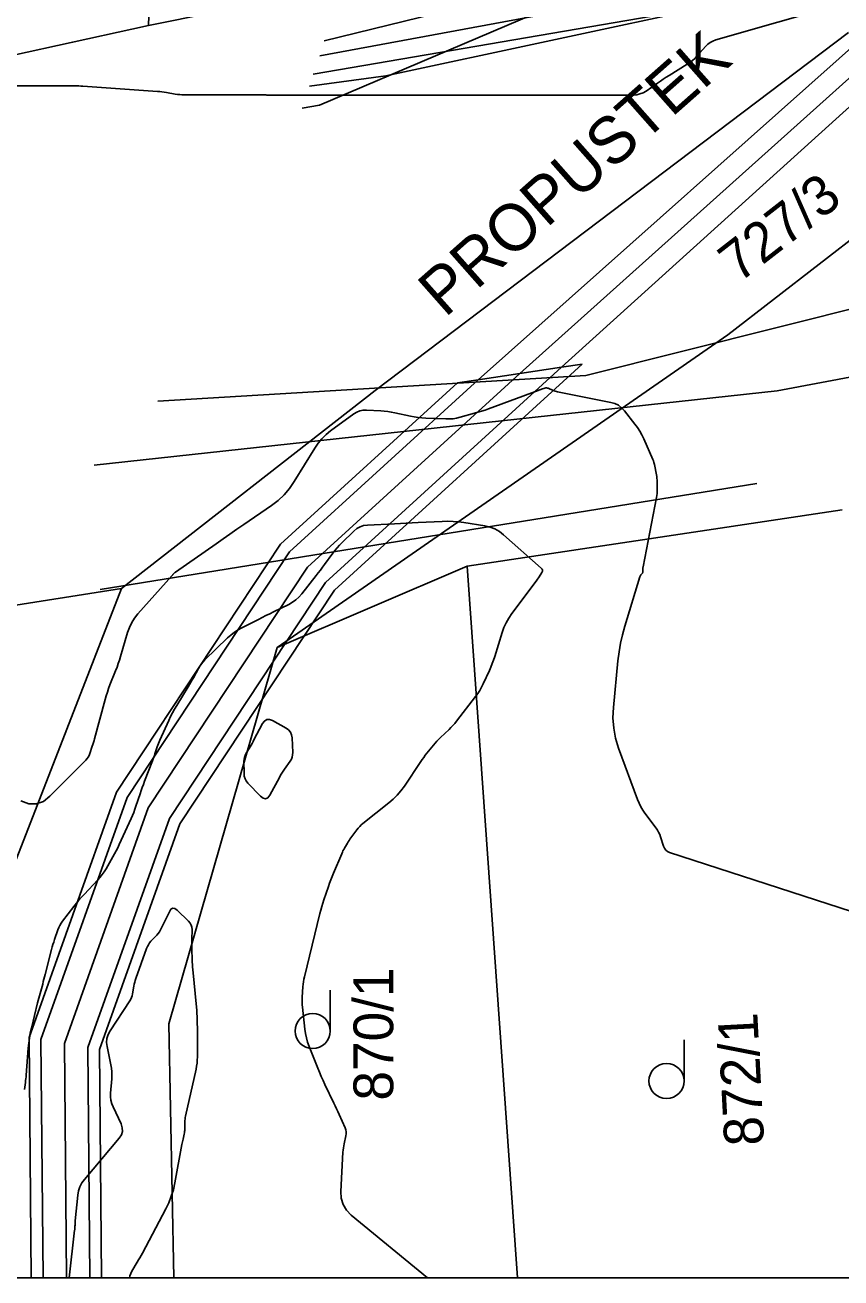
# Model space of a CAD drawing. Extents: x -534410 to -534262, y -1190162 to -1189584.
# Drawn here: x -534346.89 to -534329.45, y -1190161.97 to -1190135.2 of the extents above; entities that cross this region are included whole.
import ezdxf

# ---------------------------------------------------------------- set-up
doc = ezdxf.new("R2010")
doc.units = 0
for name, color, linetype in [('07_ELEKTRO', 7, 'Continuous'), ('14', 7, 'Continuous'), ('30', 7, 'Continuous'), ('31', 7, 'Continuous'), ('_N_osa', 7, 'Continuous'), ('_N_text', 7, 'Continuous'), ('_rámeček', 7, 'Continuous'), ('_rámeček_mřížka', 7, 'Continuous'), ('_tenka', 7, 'Continuous'), ('_tenká_čárkovaná', 7, 'Continuous'), ('Hranice parcel', 7, 'Continuous'), ('Parcelní čísla', 7, 'Continuous'), ('Vrstva 1', 7, 'Continuous'), ('Vrstva 2', 7, 'Continuous'), ('Značky kultur', 7, 'Continuous')]:
    doc.layers.add(name, color=color, linetype=linetype)

msp = doc.modelspace()

# ---------------------------------------------------------------- linework, layer by layer
at = {"layer": '07_ELEKTRO'}
for points in [[(-534340.501, -1190135.539), (-534331.273, -1190133.27), (-534330.81, -1190133.08), (-534330.32, -1190132.66), (-534330.24, -1190132.17), (-534330.24, -1190130.93), (-534330.14, -1190126.19), (-534329.99, -1190122.81), (-534329.79, -1190121.43), (-534329.75, -1190115.24), (-534329.64, -1190109.01), (-534329.39, -1190101.86), (-534329.4, -1190094.43), (-534329.31, -1190087.46), (-534329.03, -1190079.95)], [(-534331.25, -1190144.995), (-534345.285, -1190147.258)]]:
    msp.add_lwpolyline(points, dxfattribs=at)
at = {"layer": '14'}
msp.add_lwpolyline([(-534314.619, -1190129.669), (-534321.91, -1190130.93), (-534322.66, -1190131.1), (-534328.55, -1190132.02), (-534329.42, -1190132.15), (-534330.73, -1190132.71), (-534340.6, -1190136.91), (-534340.966, -1190136.972)], dxfattribs=at)
at = {"layer": '30'}
for points in [[(-534346.982, -1190151.777), (-534346.812, -1190151.837), (-534346.651, -1190151.841), (-534346.5, -1190151.787), (-534346.358, -1190151.677), (-534345.591, -1190150.904), (-534345.563, -1190150.873), (-534345.54, -1190150.84), (-534345.521, -1190150.804), (-534345.506, -1190150.765), (-534345.453, -1190150.607), (-534345.44, -1190150.568), (-534345.428, -1190150.528), (-534345.416, -1190150.488), (-534345.405, -1190150.448), (-534345.179, -1190149.609), (-534345.157, -1190149.53), (-534345.132, -1190149.453), (-534345.105, -1190149.376), (-534345.076, -1190149.299), (-534344.955, -1190148.996), (-534344.925, -1190148.92), (-534344.898, -1190148.843), (-534344.872, -1190148.766), (-534344.848, -1190148.688), (-534344.698, -1190148.178), (-534344.659, -1190148.069), (-534344.61, -1190147.967), (-534344.55, -1190147.872), (-534344.479, -1190147.782), (-534343.756, -1190146.965), (-534343.749, -1190146.958), (-534343.743, -1190146.951), (-534343.736, -1190146.944), (-534343.73, -1190146.938), (-534343.703, -1190146.912), (-534343.696, -1190146.905), (-534343.689, -1190146.899), (-534343.681, -1190146.893), (-534343.674, -1190146.888), (-534342.807, -1190146.281), (-534342.66, -1190146.178), (-534342.513, -1190146.075), (-534342.365, -1190145.973), (-534342.217, -1190145.871), (-534341.624, -1190145.464), (-534341.482, -1190145.356), (-534341.354, -1190145.235), (-534341.24, -1190145.101), (-534341.139, -1190144.954), (-534340.7, -1190144.239), (-534340.629, -1190144.134), (-534340.549, -1190144.038), (-534340.459, -1190143.95), (-534340.361, -1190143.87), (-534339.865, -1190143.506), (-534339.802, -1190143.468), (-534339.736, -1190143.441), (-534339.666, -1190143.427), (-534339.592, -1190143.425), (-534339.289, -1190143.442), (-534339.214, -1190143.447), (-534339.139, -1190143.456), (-534339.064, -1190143.468), (-534338.99, -1190143.483), (-534338.653, -1190143.557), (-534338.572, -1190143.573), (-534338.491, -1190143.586), (-534338.409, -1190143.594), (-534338.326, -1190143.599), (-534337.901, -1190143.616), (-534337.822, -1190143.616), (-534337.745, -1190143.61), (-534337.667, -1190143.598), (-534337.591, -1190143.579), (-534337.287, -1190143.495), (-534337.211, -1190143.473), (-534337.136, -1190143.45), (-534337.061, -1190143.424), (-534336.987, -1190143.398), (-534335.926, -1190143.004), (-534335.908, -1190142.998), (-534335.889, -1190142.991), (-534335.871, -1190142.985), (-534335.853, -1190142.979), (-534335.78, -1190142.956), (-534335.762, -1190142.952), (-534335.744, -1190142.951), (-534335.726, -1190142.954), (-534335.708, -1190142.96), (-534335.606, -1190143.006), (-534335.583, -1190143.016), (-534335.56, -1190143.024), (-534335.536, -1190143.031), (-534335.512, -1190143.037), (-534334.373, -1190143.26), (-534334.287, -1190143.284), (-534334.21, -1190143.322), (-534334.141, -1190143.374), (-534334.081, -1190143.439), (-534333.856, -1190143.727), (-534333.802, -1190143.801), (-534333.753, -1190143.877), (-534333.709, -1190143.957), (-534333.669, -1190144.039), (-534333.476, -1190144.478), (-534333.462, -1190144.513), (-534333.45, -1190144.548), (-534333.439, -1190144.585), (-534333.431, -1190144.621), (-534333.401, -1190144.77), (-534333.395, -1190144.807), (-534333.39, -1190144.845), (-534333.387, -1190144.882), (-534333.385, -1190144.92), (-534333.382, -1190145.116), (-534333.382, -1190145.162), (-534333.385, -1190145.207), (-534333.39, -1190145.251), (-534333.398, -1190145.296), (-534333.683, -1190146.773), (-534333.684, -1190146.78), (-534333.685, -1190146.787), (-534333.685, -1190146.794), (-534333.685, -1190146.802), (-534333.685, -1190146.831), (-534333.685, -1190146.844), (-534333.685, -1190146.858), (-534333.687, -1190146.886), (-534333.688, -1190146.893), (-534333.689, -1190146.899), (-534333.692, -1190146.905), (-534333.696, -1190146.911), (-534333.729, -1190146.949), (-534333.736, -1190146.958), (-534333.741, -1190146.967), (-534333.746, -1190146.976), (-534333.749, -1190146.986), (-534334.072, -1190148.046), (-534334.122, -1190148.227), (-534334.164, -1190148.409), (-534334.196, -1190148.594), (-534334.219, -1190148.78), (-534334.317, -1190149.782), (-534334.326, -1190150.003), (-534334.311, -1190150.221), (-534334.271, -1190150.435), (-534334.206, -1190150.647), (-534333.801, -1190151.749), (-534333.769, -1190151.826), (-534333.733, -1190151.9), (-534333.69, -1190151.972), (-534333.643, -1190152.041), (-534333.405, -1190152.36), (-534333.376, -1190152.403), (-534333.35, -1190152.448), (-534333.328, -1190152.495), (-534333.311, -1190152.544), (-534333.247, -1190152.744), (-534333.227, -1190152.79), (-534333.198, -1190152.828), (-534333.161, -1190152.857), (-534333.115, -1190152.877), (-534328.176, -1190154.481)], [(-534345.95, -1190161.97), (-534345.831, -1190160.952), (-534345.83, -1190160.941), (-534345.829, -1190160.93), (-534345.828, -1190160.919), (-534345.827, -1190160.909), (-534345.824, -1190160.864), (-534345.823, -1190160.844), (-534345.822, -1190160.825), (-534345.82, -1190160.787), (-534345.82, -1190160.778), (-534345.819, -1190160.768), (-534345.818, -1190160.759), (-534345.817, -1190160.749), (-534345.762, -1190160.199), (-534345.746, -1190160.107), (-534345.717, -1190160.02), (-534345.675, -1190159.939), (-534345.62, -1190159.863), (-534344.88, -1190158.985), (-534344.833, -1190158.913), (-534344.811, -1190158.838), (-534344.813, -1190158.76), (-534344.84, -1190158.678), (-534345.011, -1190158.317), (-534345.039, -1190158.247), (-534345.057, -1190158.174), (-534345.065, -1190158.1), (-534345.063, -1190158.025), (-534345.036, -1190157.718), (-534345.033, -1190157.641), (-534345.034, -1190157.565), (-534345.042, -1190157.49), (-534345.055, -1190157.414), (-534345.138, -1190157.025), (-534345.148, -1190156.936), (-534345.141, -1190156.851), (-534345.116, -1190156.769), (-534345.074, -1190156.691), (-534344.652, -1190156.052), (-534344.63, -1190156.016), (-534344.614, -1190155.979), (-534344.601, -1190155.94), (-534344.592, -1190155.9), (-534344.565, -1190155.735), (-534344.557, -1190155.694), (-534344.547, -1190155.653), (-534344.536, -1190155.613), (-534344.523, -1190155.574), (-534344.293, -1190154.931), (-534344.276, -1190154.889), (-534344.254, -1190154.849), (-534344.229, -1190154.812), (-534344.2, -1190154.777), (-534344.075, -1190154.642), (-534344.045, -1190154.607), (-534344.019, -1190154.571), (-534343.994, -1190154.532), (-534343.973, -1190154.492), (-534343.807, -1190154.144), (-534343.772, -1190154.093), (-534343.733, -1190154.07), (-534343.688, -1190154.077), (-534343.637, -1190154.114), (-534343.396, -1190154.347), (-534343.363, -1190154.386), (-534343.339, -1190154.429), (-534343.325, -1190154.476), (-534343.322, -1190154.527), (-534343.326, -1190154.739), (-534343.326, -1190154.792), (-534343.326, -1190154.844), (-534343.326, -1190154.897), (-534343.324, -1190154.95), (-534343.318, -1190155.166), (-534343.316, -1190155.219), (-534343.313, -1190155.273), (-534343.309, -1190155.326), (-534343.304, -1190155.38), (-534343.228, -1190156.185), (-534343.222, -1190156.251), (-534343.218, -1190156.317), (-534343.214, -1190156.383), (-534343.212, -1190156.449), (-534343.205, -1190156.713), (-534343.203, -1190156.779), (-534343.203, -1190156.845), (-534343.203, -1190156.91), (-534343.203, -1190156.976), (-534343.206, -1190157.246), (-534343.209, -1190157.313), (-534343.215, -1190157.379), (-534343.224, -1190157.445), (-534343.237, -1190157.51), (-534343.46, -1190158.51), (-534343.466, -1190158.543), (-534343.471, -1190158.576), (-534343.474, -1190158.609), (-534343.476, -1190158.643), (-534343.478, -1190158.789), (-534343.479, -1190158.817), (-534343.482, -1190158.844), (-534343.486, -1190158.871), (-534343.491, -1190158.899), (-534343.515, -1190159.007), (-534343.52, -1190159.034), (-534343.526, -1190159.061), (-534343.531, -1190159.088), (-534343.537, -1190159.116), (-534343.689, -1190159.94), (-534343.721, -1190160.085), (-534343.765, -1190160.226), (-534343.818, -1190160.363), (-534343.883, -1190160.496), (-534344.384, -1190161.439), (-534344.411, -1190161.488), (-534344.438, -1190161.537), (-534344.465, -1190161.586), (-534344.494, -1190161.634), (-534344.608, -1190161.826), (-534344.633, -1190161.875), (-534344.65, -1190161.927), (-534344.658, -1190161.97)]]:
    msp.add_lwpolyline(points, dxfattribs=at)
msp.add_lwpolyline([(-534341.193, -1190150.364), (-534341.218, -1190150.308), (-534341.257, -1190150.261), (-534341.31, -1190150.224), (-534341.605, -1190150.062), (-534341.67, -1190150.038), (-534341.727, -1190150.04), (-534341.776, -1190150.07), (-534341.817, -1190150.126), (-534341.999, -1190150.473), (-534342.019, -1190150.51), (-534342.04, -1190150.548), (-534342.061, -1190150.586), (-534342.083, -1190150.623), (-534342.171, -1190150.771), (-534342.19, -1190150.808), (-534342.204, -1190150.848), (-534342.211, -1190150.888), (-534342.214, -1190150.931), (-534342.211, -1190151.194), (-534342.205, -1190151.25), (-534342.189, -1190151.303), (-534342.164, -1190151.351), (-534342.129, -1190151.395), (-534341.86, -1190151.677), (-534341.804, -1190151.721), (-534341.752, -1190151.731), (-534341.705, -1190151.708), (-534341.662, -1190151.651), (-534341.455, -1190151.273), (-534341.429, -1190151.228), (-534341.403, -1190151.184), (-534341.374, -1190151.141), (-534341.345, -1190151.098), (-534341.226, -1190150.929), (-534341.2, -1190150.886), (-534341.182, -1190150.84), (-534341.172, -1190150.792), (-534341.17, -1190150.741), (-534341.183, -1190150.429)], close=True, dxfattribs=at)
at = {"layer": '31'}
for points in [[(-534347.07, -1190136.498), (-534346.176, -1190136.498), (-534346.003, -1190136.498), (-534345.83, -1190136.498), (-534345.786, -1190136.498), (-534345.743, -1190136.5), (-534345.7, -1190136.501), (-534345.657, -1190136.504), (-534344.06, -1190136.617), (-534344.012, -1190136.621), (-534343.964, -1190136.626), (-534343.917, -1190136.632), (-534343.87, -1190136.639), (-534343.681, -1190136.672), (-534343.633, -1190136.679), (-534343.586, -1190136.684), (-534343.538, -1190136.687), (-534343.49, -1190136.688), (-534341.939, -1190136.688), (-534341.92, -1190136.688), (-534341.9, -1190136.688), (-534341.88, -1190136.688), (-534341.861, -1190136.689), (-534341.782, -1190136.691), (-534341.763, -1190136.692), (-534341.743, -1190136.692), (-534341.723, -1190136.693), (-534341.704, -1190136.693), (-534333.892, -1190136.693), (-534333.819, -1190136.687), (-534333.75, -1190136.671), (-534333.683, -1190136.645), (-534333.62, -1190136.608), (-534333.375, -1190136.438), (-534333.313, -1190136.396), (-534333.251, -1190136.355), (-534333.188, -1190136.315), (-534333.125, -1190136.275), (-534332.739, -1190136.037), (-534332.682, -1190135.999), (-534332.629, -1190135.958), (-534332.579, -1190135.912), (-534332.531, -1190135.863), (-534332.349, -1190135.657), (-534332.301, -1190135.61), (-534332.248, -1190135.571), (-534332.19, -1190135.54), (-534332.127, -1190135.517), (-534329.478, -1190134.76)], [(-534338.288, -1190161.97), (-534339.919, -1190160.626), (-534340.023, -1190160.521), (-534340.094, -1190160.401), (-534340.134, -1190160.268), (-534340.141, -1190160.12), (-534340.096, -1190159.281), (-534340.092, -1190159.237), (-534340.087, -1190159.193), (-534340.08, -1190159.149), (-534340.072, -1190159.105), (-534340.034, -1190158.931), (-534340.028, -1190158.888), (-534340.029, -1190158.846), (-534340.036, -1190158.804), (-534340.051, -1190158.763), (-534340.18, -1190158.476), (-534340.207, -1190158.415), (-534340.235, -1190158.354), (-534340.264, -1190158.293), (-534340.292, -1190158.232), (-534340.481, -1190157.837), (-534340.521, -1190157.75), (-534340.56, -1190157.663), (-534340.598, -1190157.576), (-534340.634, -1190157.488), (-534340.82, -1190157.024), (-534340.853, -1190156.933), (-534340.879, -1190156.841), (-534340.899, -1190156.748), (-534340.913, -1190156.653), (-534340.964, -1190156.187), (-534340.969, -1190156.132), (-534340.971, -1190156.078), (-534340.972, -1190156.023), (-534340.969, -1190155.968), (-534340.955, -1190155.749), (-534340.95, -1190155.695), (-534340.943, -1190155.641), (-534340.933, -1190155.587), (-534340.921, -1190155.534), (-534340.589, -1190154.183), (-534340.57, -1190154.11), (-534340.549, -1190154.036), (-534340.527, -1190153.964), (-534340.503, -1190153.891), (-534340.406, -1190153.603), (-534340.381, -1190153.531), (-534340.355, -1190153.46), (-534340.327, -1190153.389), (-534340.298, -1190153.319), (-534340.123, -1190152.904), (-534340.11, -1190152.875), (-534340.096, -1190152.845), (-534340.081, -1190152.817), (-534340.065, -1190152.789), (-534340, -1190152.677), (-534339.983, -1190152.649), (-534339.965, -1190152.622), (-534339.947, -1190152.595), (-534339.928, -1190152.569), (-534339.799, -1190152.393), (-534339.77, -1190152.356), (-534339.739, -1190152.321), (-534339.705, -1190152.288), (-534339.669, -1190152.258), (-534339.116, -1190151.819), (-534339.023, -1190151.739), (-534338.936, -1190151.652), (-534338.857, -1190151.559), (-534338.785, -1190151.46), (-534338.435, -1190150.938), (-534338.404, -1190150.891), (-534338.371, -1190150.846), (-534338.337, -1190150.801), (-534338.303, -1190150.757), (-534338.162, -1190150.583), (-534338.127, -1190150.54), (-534338.089, -1190150.498), (-534338.051, -1190150.458), (-534338.011, -1190150.419), (-534337.83, -1190150.25), (-534337.788, -1190150.208), (-534337.747, -1190150.165), (-534337.707, -1190150.12), (-534337.67, -1190150.073), (-534337.263, -1190149.548), (-534337.216, -1190149.484), (-534337.173, -1190149.418), (-534337.134, -1190149.349), (-534337.099, -1190149.278), (-534336.967, -1190148.989), (-534336.935, -1190148.916), (-534336.906, -1190148.843), (-534336.879, -1190148.768), (-534336.854, -1190148.693), (-534336.696, -1190148.181), (-534336.657, -1190148.073), (-534336.61, -1190147.969), (-534336.553, -1190147.87), (-534336.488, -1190147.775), (-534335.97, -1190147.082), (-534335.953, -1190147.06), (-534335.937, -1190147.036), (-534335.921, -1190147.013), (-534335.906, -1190146.989), (-534335.846, -1190146.893), (-534335.835, -1190146.869), (-534335.834, -1190146.847), (-534335.842, -1190146.826), (-534335.858, -1190146.807), (-534336.664, -1190146.09), (-534336.753, -1190146.021), (-534336.85, -1190145.966), (-534336.953, -1190145.926), (-534337.063, -1190145.901), (-534337.516, -1190145.828), (-534337.63, -1190145.812), (-534337.744, -1190145.803), (-534337.858, -1190145.8), (-534337.973, -1190145.803), (-534338.493, -1190145.831), (-534338.618, -1190145.838), (-534338.743, -1190145.845), (-534338.868, -1190145.851), (-534338.993, -1190145.857), (-534339.575, -1190145.884), (-534339.656, -1190145.895), (-534339.731, -1190145.92), (-534339.8, -1190145.958), (-534339.863, -1190146.01), (-534340.118, -1190146.259), (-534340.17, -1190146.312), (-534340.22, -1190146.367), (-534340.267, -1190146.424), (-534340.313, -1190146.484), (-534340.489, -1190146.724), (-534340.533, -1190146.784), (-534340.578, -1190146.844), (-534340.623, -1190146.903), (-534340.669, -1190146.962), (-534340.978, -1190147.354), (-534341.038, -1190147.422), (-534341.103, -1190147.481), (-534341.175, -1190147.533), (-534341.254, -1190147.577), (-534341.58, -1190147.737), (-534341.661, -1190147.777), (-534341.743, -1190147.817), (-534341.824, -1190147.858), (-534341.905, -1190147.899), (-534342.255, -1190148.076), (-534342.338, -1190148.122), (-534342.417, -1190148.174), (-534342.492, -1190148.232), (-534342.563, -1190148.295), (-534343.046, -1190148.765), (-534343.085, -1190148.806), (-534343.12, -1190148.85), (-534343.152, -1190148.896), (-534343.181, -1190148.944), (-534343.29, -1190149.144), (-534343.318, -1190149.193), (-534343.346, -1190149.242), (-534343.374, -1190149.291), (-534343.404, -1190149.34), (-534343.649, -1190149.741), (-534343.695, -1190149.818), (-534343.738, -1190149.897), (-534343.779, -1190149.976), (-534343.817, -1190150.057), (-534344.008, -1190150.476), (-534344.024, -1190150.511), (-534344.039, -1190150.548), (-534344.053, -1190150.584), (-534344.065, -1190150.621), (-534344.115, -1190150.77), (-534344.127, -1190150.807), (-534344.14, -1190150.844), (-534344.154, -1190150.881), (-534344.168, -1190150.918), (-534344.336, -1190151.357), (-534344.361, -1190151.423), (-534344.385, -1190151.489), (-534344.409, -1190151.555), (-534344.431, -1190151.622), (-534344.52, -1190151.889), (-534344.543, -1190151.956), (-534344.568, -1190152.022), (-534344.595, -1190152.087), (-534344.623, -1190152.151), (-534344.877, -1190152.71), (-534344.909, -1190152.777), (-534344.941, -1190152.843), (-534344.976, -1190152.908), (-534345.012, -1190152.972), (-534345.159, -1190153.227), (-534345.198, -1190153.29), (-534345.24, -1190153.35), (-534345.285, -1190153.407), (-534345.334, -1190153.462), (-534345.627, -1190153.774), (-534345.684, -1190153.836), (-534345.74, -1190153.9), (-534345.794, -1190153.964), (-534345.846, -1190154.031), (-534346.089, -1190154.346), (-534346.12, -1190154.39), (-534346.147, -1190154.436), (-534346.171, -1190154.485), (-534346.19, -1190154.535), (-534346.26, -1190154.741), (-534346.277, -1190154.793), (-534346.294, -1190154.845), (-534346.309, -1190154.897), (-534346.323, -1190154.95), (-534346.461, -1190155.487), (-534346.474, -1190155.538), (-534346.487, -1190155.588), (-534346.501, -1190155.638), (-534346.514, -1190155.689), (-534346.569, -1190155.89), (-534346.583, -1190155.94), (-534346.596, -1190155.991), (-534346.609, -1190156.041), (-534346.622, -1190156.092), (-534346.755, -1190156.633), (-534346.779, -1190156.739), (-534346.798, -1190156.846), (-534346.813, -1190156.954), (-534346.824, -1190157.062), (-534346.867, -1190157.638), (-534346.87, -1190157.676), (-534346.874, -1190157.715), (-534346.879, -1190157.753), (-534346.884, -1190157.791), (-534346.906, -1190157.942)]]:
    msp.add_lwpolyline(points, dxfattribs=at)
at = {"layer": '_N_osa'}
for points in [[(-534336.316, -1190142.642), (-534327.357, -1190134.604)], [(-534346.007, -1190161.97), (-534346.05, -1190156.962), (-534344.257, -1190151.926), (-534340.855, -1190146.785), (-534336.316, -1190142.642)]]:
    msp.add_lwpolyline(points, dxfattribs=at)
at = {"layer": '_rámeček'}
msp.add_lwpolyline([(-534410.126, -1190161.97), (-534261.626, -1190161.97), (-534261.626, -1189584.47)], dxfattribs=at)
at = {"layer": '_rámeček_mřížka'}
msp.add_lwpolyline([(-534410.126, -1190161.97), (-534261.626, -1190161.97), (-534261.626, -1189584.47)], dxfattribs=at)
at = {"layer": '_tenka'}
for p, q in [((-534340.592, -1190135.853), (-534314.669, -1190131.063)), ((-534335.428, -1190142.509), (-534334.985, -1190142.442)), ((-534337.204, -1190142.776), (-534335.428, -1190142.509)), ((-534337.648, -1190142.843), (-534337.204, -1190142.776))]:
    msp.add_line(p, q, dxfattribs=at)
for points in [[(-534344.053, -1190143.233), (-534334.908, -1190142.684), (-534316.418, -1190138.053)], [(-534345.413, -1190144.601), (-534330.814, -1190143.012), (-534315.851, -1190140.2)], [(-534345.257, -1190161.97), (-534345.299, -1190157.088), (-534343.581, -1190152.264), (-534340.28, -1190147.276), (-534334.985, -1190142.442)], [(-534345.507, -1190161.97), (-534345.55, -1190157.046), (-534343.807, -1190152.151), (-534340.472, -1190147.113), (-534335.428, -1190142.509)], [(-534346.757, -1190161.97), (-534346.801, -1190156.835), (-534344.933, -1190151.588), (-534341.429, -1190146.294), (-534337.648, -1190142.843)], [(-534346.507, -1190161.97), (-534346.551, -1190156.878), (-534344.708, -1190151.701), (-534341.237, -1190146.457), (-534337.204, -1190142.776)]]:
    msp.add_lwpolyline(points, dxfattribs=at)
at = {"layer": '_tenká_čárkovaná'}
for points in [[(-534335.428, -1190142.509), (-534326.521, -1190134.45)], [(-534337.204, -1190142.776), (-534328.194, -1190134.759)]]:
    msp.add_lwpolyline(points, dxfattribs=at)
at = {"layer": 'Hranice parcel'}
for p, q in [((-534343.76, -1190119.63), (-534344.25, -1190135.21)), ((-534344.25, -1190135.21), (-534351.82, -1190136.86)), ((-534329.43, -1190145.56), (-534337.44, -1190146.76)), ((-534337.44, -1190146.76), (-534341.5, -1190148.5)), ((-534336.37, -1190161.97), (-534337.44, -1190146.76)), ((-534344.83, -1190147.24), (-534349.24, -1190147.93))]:
    msp.add_line(p, q, dxfattribs=at)
for points in [[(-534344.25, -1190135.21), (-534336.14, -1190133.57), (-534336.13, -1190133.02), (-534334.08, -1190133.08), (-534334.05, -1190131.9), (-534331.23, -1190131.88)], [(-534322.11, -1190134.26), (-534331.87, -1190141.82), (-534341.5, -1190148.5)], [(-534344.83, -1190147.24), (-534339.41, -1190143.01), (-534329.29, -1190135.36)], [(-534348.046, -1190161.97), (-534348.39, -1190156.38), (-534344.83, -1190147.24)], [(-534341.5, -1190148.5), (-534343.82, -1190156.54), (-534343.711, -1190161.97)]]:
    msp.add_lwpolyline(points, dxfattribs=at)
at = {"layer": 'Vrstva 1'}
msp.add_lwpolyline([(-534331.19, -1190131.62), (-534332.13, -1190134.77), (-534339.18, -1190136.28), (-534340.815, -1190136.506)], dxfattribs=at)
at = {"layer": 'Vrstva 2'}
msp.add_lwpolyline([(-534340.731, -1190136.249), (-534320.329, -1190132.749), (-534314.58, -1190131.758)], dxfattribs=at)
at = {"layer": 'Značky kultur'}
for p, q in [((-534340.369, -1190156.694), (-534340.369, -1190155.819)), ((-534332.807, -1190157.76), (-534332.807, -1190156.885))]:
    msp.add_line(p, q, dxfattribs=at)
for centre in [(-534340.744, -1190156.694), (-534333.182, -1190157.76)]:
    msp.add_circle(centre, 0.375, dxfattribs=at)

# ---------------------------------------------------------------- texts
at = {"layer": '_N_text'}
msp.add_text('PROPUSTEK', height=1, rotation=41.4743, dxfattribs=at).set_placement((-534337.917, -1190141.466))
at = {"layer": 'Parcelní čísla'}
for s, rotation, p in [('727/3', 37.8364, (-534331.637, -1190140.725)), ('870/1', 90, (-534339.022, -1190158.18)), ('872/1', 93, (-534331.094, -1190159.126))]:
    msp.add_text(s, height=0.85, rotation=rotation, dxfattribs=at).set_placement(p)

doc.saveas('drawing.dxf')
